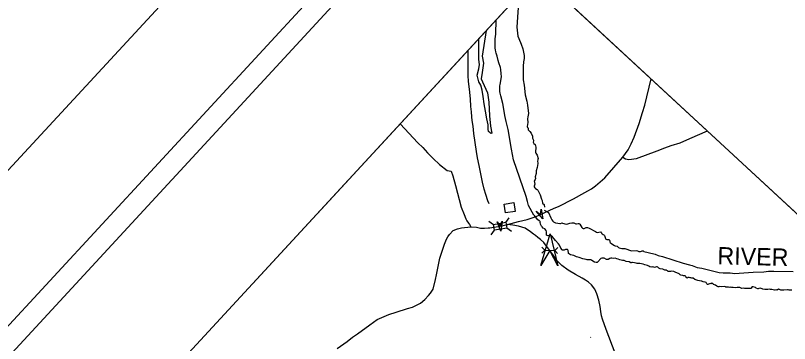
# Model space of a CAD drawing. Extents: x 1766669 to 1770980, y 998119 to 1002502.
# Drawn here: x 1767070.6 to 1767473.1, y 1000100.2 to 1000270.6 of the extents above; entities that cross this region are included whole.
import ezdxf

# ---------------------------------------------------------------- set-up
doc = ezdxf.new("R2010")
doc.units = 0
for name, color, linetype in [('CTL Vertical Benchmark CELL', 7, 'Continuous'), ('Default', 7, 'Continuous'), ('Default Symbol CELL', 7, 'Continuous'), ('Exist DTM Breakline', 7, 'Continuous'), ('Exist DTM Breakline Underwater', 7, 'Continuous'), ('Exist Property Text', 7, 'Continuous'), ('Exist Roads EOP Other', 7, 'Continuous'), ('Exist Roads EOT', 7, 'Continuous'), ('Exist Structure Minor Drop Inlet', 7, 'Continuous'), ('Exist Structure Minor Head and End Wall', 7, 'Continuous'), ('Exist Structure Minor Pipes RCP 15 Inch', 7, 'Continuous'), ('Exist Utilities Telephone Pole CELL', 7, 'Continuous'), ('PH Exist DTM Breakline', 7, 'Continuous')]:
    doc.layers.add(name, color=color, linetype=linetype)

msp = doc.modelspace()

# ---------------------------------------------------------------- linework, layer by layer
at = {"layer": 'CTL Vertical Benchmark CELL'}
for points in [[(1767316.84, 1000172.81), (1767316.26, 1000174.33), (1767315.17, 1000177.58), (1767314.39, 1000180.42), (1767313.47, 1000183.97), (1767312.57, 1000188.31), (1767311.73, 1000192.73), (1767310.85, 1000196.71), (1767310.3, 1000199.91), (1767308.91, 1000209.3), (1767308.58, 1000213.13), (1767308.16, 1000216.09), (1767307.96, 1000217.91), (1767307.68, 1000220.64), (1767307.45, 1000223.39), (1767307.13, 1000227.25), (1767306.62, 1000232.41), (1767306.23, 1000236.29), (1767306.05, 1000239.39), (1767306.08, 1000241.7), (1767305.98, 1000244.5), (1767305.94, 1000252.6)], [(1767369.7, 1000103.34), (1767369.59, 1000103.54)]]:
    msp.add_lwpolyline(points, dxfattribs=at)
at = {"layer": 'Default'}
msp.add_lwpolyline([(1766911.45, 999825.82), (1767342.39, 1000292.03), (1767769.56, 999897.17), (1767338.62, 999430.96)], close=True, dxfattribs=at)
at = {"layer": 'Default Symbol CELL'}
for p, q in [((1769179.89, 1002395.47), (1766757.68, 999775.07)), ((1769180.49, 1002379.93), (1766847.82, 999856.35)), ((1766911.45, 999825.82), (1767342.36, 1000292.01)), ((1767342.36, 1000292.01), (1767826.53, 999844.47))]:
    msp.add_line(p, q, dxfattribs=at)
at = {"layer": 'Exist DTM Breakline'}
for points in [[(1767386.34, 1000197.02), (1767389.28, 1000200.77), (1767390.78, 1000203.98), (1767392.27, 1000207.46), (1767394.9, 1000214.57), (1767396.62, 1000220.24), (1767397.87, 1000224.05), (1767401.19, 1000237.67)], [(1767270.56, 1000214.32), (1767279.9, 1000204.48), (1767282.42, 1000202.01), (1767284.84, 1000199.3), (1767287.8, 1000196.37), (1767291.05, 1000193.27), (1767295.02, 1000190.17), (1767297.23, 1000189.69), (1767298.02, 1000187.38), (1767299.49, 1000182.33), (1767302.38, 1000171.02), (1767303.85, 1000167.15), (1767304.81, 1000164.96), (1767305.39, 1000163.97), (1767306.1, 1000162.72), (1767306.65, 1000162.01), (1767307.37, 1000160.87)], [(1767343.68, 1000167.28), (1767350.69, 1000170.53), (1767352.92, 1000171.43), (1767360.81, 1000175.38), (1767366.6, 1000178.65), (1767368.19, 1000179.53), (1767370.18, 1000180.6), (1767372.21, 1000182.19), (1767377.05, 1000186.33), (1767386.34, 1000197.02)], [(1767326.43, 1000161.96), (1767332.23, 1000163.61), (1767336.71, 1000164.68), (1767341.36, 1000166.24), (1767343.68, 1000167.28)], [(1767237.94, 1000097.55), (1767243.03, 1000101.29), (1767245.88, 1000103.51), (1767248.52, 1000105.23), (1767254.8, 1000109.86), (1767258.72, 1000112.59), (1767263.46, 1000114.66), (1767264.77, 1000115.23), (1767268.59, 1000116.46), (1767274.46, 1000118.41), (1767277.01, 1000119.1), (1767281.2, 1000121.11), (1767283.49, 1000123.06), (1767285.43, 1000125.14), (1767286.44, 1000126.28), (1767287.11, 1000127.45), (1767287.72, 1000128.45), (1767289.04, 1000133.39), (1767289.5, 1000135.9), (1767291.22, 1000144.6), (1767293.67, 1000151.83), (1767294.71, 1000154.39), (1767295.37, 1000155.69), (1767296.27, 1000156.88), (1767298.17, 1000158.96), (1767300.52, 1000159.83), (1767302.45, 1000160.38), (1767307.37, 1000160.87)], [(1767307.37, 1000160.87), (1767310.37, 1000160.64), (1767312.4, 1000160.17), (1767314.54, 1000160.1), (1767316.33, 1000160.24), (1767317.31, 1000160.34), (1767320.54, 1000160.74), (1767322.72, 1000161.09)], [(1767322.72, 1000161.09), (1767326.43, 1000161.96)], [(1767385.7, 1000086.52), (1767377.73, 1000107.42), (1767375.84, 1000112.76), (1767375.32, 1000114.64), (1767374.96, 1000116.78), (1767374.57, 1000119.47), (1767373.97, 1000122.69), (1767372.89, 1000125.95), (1767371.8, 1000128.45), (1767370.12, 1000130.61), (1767368.53, 1000132.11), (1767366.97, 1000133.1), (1767365.3, 1000134.2), (1767361.86, 1000136.04), (1767357.95, 1000138.26), (1767354.77, 1000140.65), (1767351.99, 1000143.51), (1767350.3, 1000145.93), (1767348.45, 1000148.6), (1767346.19, 1000151.55), (1767345.32, 1000152.67), (1767343.63, 1000154.23), (1767342.31, 1000155.34), (1767341.02, 1000156.31), (1767340.02, 1000157.05), (1767338.38, 1000158.18), (1767335.61, 1000160.05), (1767332.15, 1000161.25), (1767329.21, 1000161.68), (1767326.43, 1000161.96)]]:
    msp.add_lwpolyline(points, dxfattribs=at)
at = {"layer": 'Exist DTM Breakline Underwater'}
msp.add_lwpolyline([(1767386.34, 1000197.02), (1767387.74, 1000196.13), (1767389.53, 1000195.83), (1767393.53, 1000196.28), (1767404.3, 1000200.31), (1767408.31, 1000201.84), (1767411.56, 1000203.05), (1767416.29, 1000204.44), (1767421.22, 1000206.71), (1767430.39, 1000210.69)], dxfattribs=at)
at = {"layer": 'Exist Property Text'}
for p, q in [((1767316.79, 1000163.77), (1767319.21, 1000162.06)), ((1767325.62, 1000163.15), (1767327.33, 1000165.57)), ((1767326.13, 1000160.22), (1767328.55, 1000158.51)), ((1767318.02, 1000156.64), (1767319.73, 1000159.07))]:
    msp.add_line(p, q, dxfattribs=at)
msp.add_lwpolyline([(1767319.21, 1000162.06), (1767325.62, 1000163.16), (1767326.14, 1000160.17), (1767319.73, 1000159.07)], close=True, dxfattribs=at)
at = {"layer": 'Exist Roads EOP Other'}
for points in [[(1767343.91, 1000170.07), (1767344.76, 1000164.89), (1767341.43, 1000168.95), (1767343.68, 1000167.28)], [(1767323.73, 1000163.69), (1767323.07, 1000158.49), (1767321.04, 1000163.33), (1767322.72, 1000161.09)]]:
    msp.add_lwpolyline(points, close=True, dxfattribs=at)
at = {"layer": 'Exist Roads EOT'}
for p, q in [((1767332.35, 1000281.18), (1767331.28, 1000264.5)), ((1767336.87, 1000173.91), (1767336.2, 1000176.58))]:
    msp.add_line(p, q, dxfattribs=at)
for points in [[(1767321.66, 1000247.28), (1767321.1, 1000249.59), (1767320.63, 1000251.13), (1767320.43, 1000251.72), (1767320.2, 1000252.82), (1767320.11, 1000253.6), (1767319.99, 1000255.97), (1767320.09, 1000257.33), (1767320.08, 1000258.46), (1767320.33, 1000260.95), (1767320.51, 1000268.36)], [(1767331.28, 1000264.5), (1767331.89, 1000259.98), (1767332.32, 1000258.65), (1767333.59, 1000255.73), (1767334.39, 1000253.39), (1767335.05, 1000249.84), (1767335.14, 1000249.14), (1767335.08, 1000248.26), (1767334.78, 1000246.56), (1767334.66, 1000244.38), (1767334.66, 1000237.22), (1767335.07, 1000234.48), (1767335.65, 1000229.49), (1767336.47, 1000226.06), (1767336.81, 1000224.04), (1767337.3, 1000219.76), (1767337.26, 1000218.8), (1767337, 1000217.96), (1767336.82, 1000216.9), (1767336.94, 1000214.99), (1767336.74, 1000212.97), (1767336.86, 1000212.47), (1767337.13, 1000212.15), (1767337.24, 1000211.18), (1767338.05, 1000210.36)], [(1767315.33, 1000262.76), (1767313.22, 1000249.57), (1767313.9, 1000245.94), (1767313.29, 1000241.06), (1767312.79, 1000237.68), (1767313.48, 1000236.15), (1767316.09, 1000230.38), (1767316.74, 1000225.55), (1767317.12, 1000218.48), (1767317.61, 1000213.2), (1767318.29, 1000209.57), (1767317.8, 1000209.32), (1767317.42, 1000209.67), (1767316.63, 1000210.34), (1767316.41, 1000211.62), (1767316.46, 1000213.82), (1767315.73, 1000216.98), (1767315.01, 1000220.98), (1767314.33, 1000224.81), (1767313.87, 1000228.53), (1767313.34, 1000231.77), (1767312.64, 1000234.4), (1767311.54, 1000236.25), (1767310.7, 1000239.71), (1767311.62, 1000242.99), (1767311.97, 1000245.16), (1767311.5, 1000247.7), (1767311.62, 1000258.75)], [(1767322.54, 1000234.08), (1767322.62, 1000234.82), (1767323.23, 1000237.72), (1767323.29, 1000238.88), (1767323.23, 1000240.25), (1767322.97, 1000242.58), (1767322.79, 1000243.56), (1767322, 1000246), (1767321.66, 1000247.28)], [(1767325.14, 1000218.66), (1767324.65, 1000220.88), (1767324.1, 1000224.94), (1767323.06, 1000228.91), (1767322.59, 1000230.28), (1767322.46, 1000231.08), (1767322.54, 1000234.08)], [(1767336.2, 1000176.58), (1767329.65, 1000195.72), (1767328.61, 1000201.17), (1767326.82, 1000211.4), (1767325.81, 1000215.64), (1767325.14, 1000218.66)], [(1767338.05, 1000210.36), (1767338.7, 1000209.44), (1767339.38, 1000207.88), (1767339.47, 1000207.52), (1767339.51, 1000206.96), (1767339.94, 1000205.93), (1767340.01, 1000205.52), (1767339.87, 1000204.87), (1767339.91, 1000204.45), (1767340.07, 1000204.18), (1767340.8, 1000203.55), (1767341.07, 1000202.93), (1767341.15, 1000202.17), (1767340.95, 1000199.62), (1767341.14, 1000199.15), (1767341.56, 1000198.62), (1767341.84, 1000198.11), (1767342.34, 1000196.34), (1767342.31, 1000195.75), (1767342.09, 1000194.71), (1767342.25, 1000194.12), (1767342.26, 1000193.79), (1767341.88, 1000191.63), (1767341.42, 1000189.86), (1767341.28, 1000188.52), (1767340.86, 1000186.78), (1767341.06, 1000185.93), (1767340.84, 1000185.38), (1767340.35, 1000184.48), (1767340.41, 1000183.81), (1767340.6, 1000182.96), (1767340.27, 1000181.99), (1767340.24, 1000181.6), (1767340.67, 1000181.07), (1767341.09, 1000180.73), (1767341.88, 1000180.25), (1767342.14, 1000179.95), (1767342.82, 1000178.84), (1767343.47, 1000177.47), (1767344.07, 1000175.28), (1767344.41, 1000174.58), (1767344.67, 1000173.15), (1767344.82, 1000172.93), (1767345.49, 1000172.36), (1767345.58, 1000172.11), (1767345.69, 1000171.21), (1767345.68, 1000171.08)], [(1767340.16, 1000166.88), (1767337.37, 1000171.95), (1767336.87, 1000173.91)], [(1767345.6, 1000169.55), (1767347.74, 1000168.19), (1767349.06, 1000165.48)], [(1767340.16, 1000166.88), (1767341.52, 1000165.16), (1767342.96, 1000164.08), (1767343.31, 1000163.7), (1767343.46, 1000163.43), (1767343.49, 1000163.24)], [(1767348.8, 1000156.25), (1767347.56, 1000156.17), (1767347, 1000156.32), (1767346.8, 1000156.48), (1767346.71, 1000156.67), (1767346.7, 1000157.03), (1767346.81, 1000158.23), (1767346.62, 1000158.89), (1767345.79, 1000159.71), (1767344.93, 1000160.17), (1767344.48, 1000160.81), (1767344.11, 1000161.2), (1767343.58, 1000162.16), (1767343.49, 1000163.24)], [(1767349.06, 1000165.48), (1767349.49, 1000164.52), (1767349.98, 1000163.81), (1767350.34, 1000163.5), (1767351.08, 1000163.05), (1767351.48, 1000162.94), (1767352.64, 1000162.77), (1767353.62, 1000162.49), (1767353.98, 1000162.54), (1767354.81, 1000162.81), (1767355.13, 1000162.79), (1767357.01, 1000162.22), (1767357.83, 1000162.31), (1767358.92, 1000162.72), (1767359.95, 1000162.98), (1767360.94, 1000162.81), (1767361.91, 1000162.46), (1767362.25, 1000162.43), (1767363.17, 1000162.59), (1767363.59, 1000162.54), (1767363.86, 1000162.39), (1767364.15, 1000162.12), (1767365.07, 1000160.55), (1767365.5, 1000160.15), (1767365.77, 1000160), (1767366.01, 1000159.94), (1767366.31, 1000159.97), (1767367.33, 1000160.41), (1767367.77, 1000160.49), (1767368.11, 1000160.49), (1767368.99, 1000160.17), (1767372.19, 1000158.32), (1767372.8, 1000158.04), (1767373.17, 1000157.95), (1767373.98, 1000158), (1767374.98, 1000158.24)], [(1767355.03, 1000148.74), (1767354.81, 1000148.84), (1767354.13, 1000149.74), (1767353.46, 1000151.28), (1767353.03, 1000152.04), (1767351.38, 1000153.72), (1767349.83, 1000155.61), (1767349.24, 1000156.1), (1767348.8, 1000156.25)], [(1767374.98, 1000158.24), (1767375.17, 1000158.1), (1767375.32, 1000157.57), (1767375.64, 1000157.12), (1767376.12, 1000156.79), (1767376.58, 1000156.6), (1767376.87, 1000156.31), (1767377.34, 1000154.75), (1767377.65, 1000154.4), (1767378.13, 1000154.15), (1767378.73, 1000154.22), (1767379.32, 1000154.16), (1767379.69, 1000153.62), (1767379.69, 1000152.99), (1767379.9, 1000152.71), (1767380.7, 1000152.04), (1767382.06, 1000151.06), (1767382.5, 1000150.87), (1767383.44, 1000150.74), (1767383.66, 1000150.61), (1767384.22, 1000150.02), (1767384.5, 1000149.85), (1767385.28, 1000149.72), (1767385.96, 1000149.48), (1767387.45, 1000149.5), (1767387.97, 1000149.45), (1767390.41, 1000148.57), (1767391.07, 1000148.43), (1767393.34, 1000148.48), (1767394.05, 1000148.27), (1767394.79, 1000147.95), (1767395.62, 1000147.95), (1767396.17, 1000148.1), (1767396.51, 1000148.28), (1767396.99, 1000148.29), (1767397.35, 1000148.04), (1767399.62, 1000147.41), (1767403.16, 1000146.66), (1767404.83, 1000146), (1767407.07, 1000145.45), (1767417.77, 1000141.98), (1767421.05, 1000141.05), (1767422.49, 1000140.77), (1767425.11, 1000139.75), (1767427.53, 1000139.27), (1767433.75, 1000137.72), (1767436.56, 1000137.16), (1767438.52, 1000136.94), (1767442.31, 1000136.87), (1767443.47, 1000136.68), (1767444.42, 1000136.62), (1767454.24, 1000137.24), (1767459.68, 1000137.36), (1767462.17, 1000137.72), (1767464.93, 1000137.83), (1767475.04, 1000137.62)], [(1767358.15, 1000147.24), (1767358, 1000148.54), (1767357.9, 1000148.8), (1767357.65, 1000149.07), (1767357.12, 1000149.11), (1767356.67, 1000149.03), (1767355.99, 1000148.68), (1767355.5, 1000148.66), (1767355.03, 1000148.74)], [(1767363.03, 1000144.97), (1767362.29, 1000145.22), (1767360.95, 1000145.87), (1767360.1, 1000146.17), (1767359.28, 1000146.35), (1767358.62, 1000146.61), (1767358.23, 1000147), (1767358.15, 1000147.24)], [(1767390.58, 1000142.12), (1767389.78, 1000142.58), (1767388.22, 1000142.72), (1767387.08, 1000143.36), (1767386.26, 1000143.4), (1767385.63, 1000143.46), (1767384.85, 1000143.65), (1767383.98, 1000144.07), (1767383.29, 1000144.14), (1767382.41, 1000144.45), (1767381.55, 1000144.3), (1767380.73, 1000144.5), (1767380.11, 1000144.52), (1767379.7, 1000144.37), (1767378.86, 1000143.85), (1767378.36, 1000143.76), (1767377.85, 1000143.88), (1767376.66, 1000144.5), (1767375.87, 1000144.61), (1767375.54, 1000144.54), (1767375.03, 1000144.3), (1767373.34, 1000142.56), (1767373.01, 1000142.33), (1767372.53, 1000142.22), (1767371.76, 1000142.4), (1767370.34, 1000143.37), (1767369.71, 1000143.64), (1767367.81, 1000143.75), (1767367.31, 1000143.9), (1767365.54, 1000144.2), (1767363.71, 1000144.85), (1767363.03, 1000144.97)], [(1767399.17, 1000140.77), (1767398.59, 1000140.97), (1767397.79, 1000141.11), (1767396.95, 1000141.43), (1767395.18, 1000141.71), (1767393.86, 1000141.79), (1767393.29, 1000141.89), (1767392.53, 1000142.17), (1767391.51, 1000142.28), (1767391.11, 1000142.26), (1767390.8, 1000142.12), (1767390.58, 1000142.12)], [(1767413.58, 1000137.33), (1767412.96, 1000137.62), (1767411.76, 1000137.72), (1767411.15, 1000137.62), (1767410.51, 1000137.64), (1767410.07, 1000137.54), (1767409.79, 1000137.67), (1767409.58, 1000137.93), (1767409.3, 1000138.06), (1767409.2, 1000138.22), (1767408.97, 1000138.36), (1767408.28, 1000138.34), (1767407.92, 1000138.39), (1767407.23, 1000138.82), (1767405.78, 1000139.02), (1767405.13, 1000139.4), (1767404.66, 1000139.87), (1767404.21, 1000140), (1767403.91, 1000140), (1767402.93, 1000139.77), (1767402.49, 1000139.8), (1767401.86, 1000139.99), (1767401.5, 1000139.94), (1767400.54, 1000140.01), (1767399.94, 1000140.43), (1767399.17, 1000140.77)], [(1767474.33, 1000127.98), (1767472.87, 1000127.92), (1767472.44, 1000128.02), (1767472.01, 1000128.03), (1767470.08, 1000127.92), (1767469.76, 1000127.97), (1767469.18, 1000127.87), (1767468.57, 1000127.95), (1767467.83, 1000128.33), (1767467.45, 1000128.39), (1767466.73, 1000127.99), (1767466.32, 1000128.06), (1767465.57, 1000127.82), (1767465.28, 1000127.84), (1767464.62, 1000128.13), (1767463.83, 1000128.29), (1767463.51, 1000128.21), (1767463.13, 1000128.23), (1767462.81, 1000128.37), (1767461.79, 1000128.21), (1767461.35, 1000128.19), (1767460.84, 1000128.31), (1767460.34, 1000128.23), (1767459.3, 1000128.4), (1767458, 1000128.9), (1767457.1, 1000128.81), (1767456.85, 1000128.61), (1767456.59, 1000128.56), (1767455.77, 1000128.88), (1767455.44, 1000129.21), (1767454.22, 1000129.65), (1767454.01, 1000129.67), (1767453.56, 1000129.61), (1767453.45, 1000129.53), (1767453.21, 1000128.99), (1767453.03, 1000128.84), (1767452.72, 1000128.76), (1767450.97, 1000128.74), (1767449.87, 1000128.79), (1767449.3, 1000128.92), (1767448.27, 1000128.83), (1767447.27, 1000129.29), (1767447.02, 1000129.34), (1767446.77, 1000129.27), (1767445.94, 1000129.34), (1767445.01, 1000129.19), (1767443.82, 1000129.34), (1767443.05, 1000129.3), (1767442.61, 1000129.38), (1767441.98, 1000129.31), (1767441.29, 1000129.51), (1767440.98, 1000129.52), (1767440.39, 1000129.41), (1767440.07, 1000129.46), (1767439.74, 1000129.67), (1767439.32, 1000129.81), (1767437.73, 1000129.66), (1767436.9, 1000129.74), (1767436.31, 1000129.65), (1767435.98, 1000129.68), (1767435.32, 1000130), (1767434.63, 1000130.53), (1767433.6, 1000130.84), (1767433.34, 1000131.23), (1767433.18, 1000131.37), (1767432.92, 1000131.45), (1767432.66, 1000131.46), (1767432.24, 1000131.24), (1767431.91, 1000131.35), (1767430.65, 1000130.81), (1767430.4, 1000130.87), (1767430.03, 1000131.12), (1767429.7, 1000131.82), (1767429.29, 1000132.11), (1767428.27, 1000132.18), (1767427.58, 1000132.52), (1767427.2, 1000132.51), (1767425.44, 1000133.01), (1767423.95, 1000133.49), (1767423.04, 1000134.13), (1767422.26, 1000134.12), (1767421.84, 1000134.29), (1767421.43, 1000134.27), (1767420.91, 1000134.46), (1767420.25, 1000134.42), (1767420.08, 1000134.27), (1767419.84, 1000134.22), (1767419.44, 1000134.45), (1767419.29, 1000134.6), (1767419.1, 1000135), (1767418.76, 1000135.27), (1767418.59, 1000135.36), (1767418, 1000135.44), (1767417.67, 1000135.6), (1767416.58, 1000135.65), (1767416.25, 1000135.82), (1767415.64, 1000136.44), (1767415.44, 1000136.57), (1767413.95, 1000137.01), (1767413.58, 1000137.33)]]:
    msp.add_lwpolyline(points, dxfattribs=at)
at = {"layer": 'Exist Structure Minor Head and End Wall'}
for p, q in [((1767344.32, 1000147.08), (1767345.85, 1000148.64)), ((1767344.37, 1000150.25), (1767345.85, 1000148.64)), ((1767345.85, 1000148.64), (1767351.05, 1000148.56)), ((1767352.58, 1000150.12), (1767351.05, 1000148.56)), ((1767352.53, 1000146.95), (1767351.05, 1000148.56))]:
    msp.add_line(p, q, dxfattribs=at)
at = {"layer": 'Exist Structure Minor Pipes RCP 15 Inch'}
msp.add_lwpolyline([(1767324.76, 1000172.58), (1767329.71, 1000173.39), (1767330.44, 1000168.87), (1767325.49, 1000168.07)], close=True, dxfattribs=at)
at = {"layer": 'Exist Utilities Telephone Pole CELL'}
msp.add_lwpolyline([(1767343.79, 1000140.7), (1767348.68, 1000157.2), (1767352.69, 1000140.47), (1767348.45, 1000148.6)], close=True, dxfattribs=at)
at = {"layer": 'PH Exist DTM Breakline'}
msp.add_lwpolyline([(1766668.62, 999760.16), (1769205.64, 1002501.94), (1770979.75, 1000860.32), (1768442.74, 998118.54)], close=True, dxfattribs=at)

# ---------------------------------------------------------------- texts
at = {"layer": 'Exist Structure Minor Drop Inlet'}
msp.add_text('RIVER', height=9.033, rotation=358.647, dxfattribs=at).set_placement((1767435.53, 1000141.32))

doc.saveas('drawing.dxf')
